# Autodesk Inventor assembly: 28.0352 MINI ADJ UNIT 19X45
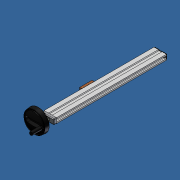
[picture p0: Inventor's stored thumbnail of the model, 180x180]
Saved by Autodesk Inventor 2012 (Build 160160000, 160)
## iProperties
Created: 2015-11
Part Number: 28.0352 MINI ADJ UNIT 19X45
Document SubType Name: Assembly
Designer: Admin
Author: Admin
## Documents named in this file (8)
- C:\Andys Backup Data\ANDY'S INVENTOR\INVENTOR LIBRARIES\PARTS LIBRARY\READY FOR USE MODULES LG\28.0352 MINI ADJ UNIT 19X45.iam
- C:\Andys Backup Data\ANDY'S INVENTOR\INVENTOR LIBRARIES\PARTS LIBRARY\READY FOR USE MODULES LG\SUBCOMPONENTS\28.0352 MINI ADJ UNIT 19X45 PROFILE.ipt
- C:\Andys Backup Data\ANDY'S INVENTOR\INVENTOR LIBRARIES\PARTS LIBRARY\READY FOR USE MODULES LG\28.0350 MINI ADJ UNIT FITTING KIT.iam
- C:\Andys Backup Data\ANDY'S INVENTOR\INVENTOR LIBRARIES\PARTS LIBRARY\END CAPS\22.1001_1 END CAP 19X45.iam
- C:\Andys Backup Data\ANDY'S INVENTOR\INVENTOR LIBRARIES\PARTS LIBRARY\READY FOR USE MODULES LG\SUBCOMPONENTS\28.0212 HANDWHEEL 80mm.iam
- C:\Andys Backup Data\ANDY'S INVENTOR\INVENTOR LIBRARIES\PARTS LIBRARY\READY FOR USE MODULES LG\SUBCOMPONENTS\19.0100_6 BUSHING.ipt
- C:\Andys Backup Data\ANDY'S INVENTOR\INVENTOR LIBRARIES\PARTS LIBRARY\READY FOR USE MODULES LG\SUBCOMPONENTS\28.0366 MINI ADJ BEARING SUPPORT 19X45.ipt
- C:\Andys Backup Data\ANDY'S INVENTOR\INVENTOR LIBRARIES\PARTS LIBRARY\FASTENING ELEMENTS\SCREWS CAP\21.1200 M8X16.ipt
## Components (7 placed, 7 different names)
1. 28.0352 MINI ADJ UNIT 19X45 PROFILE:1 — Insert:1, Angle:1, Insert:2, Angle:4, Angle:5
2. 28.0350 MINI ADJ UNIT FITTING KIT:1 [sub-assembly] — Mate:3, Angle:3, Mate:4, Insert:4, Angle:5
3. 22.1001_1 END CAP 19X45:1 [sub-assembly] — Insert:1, Angle:1
4. 28.0212 HANDWHEEL 80mm:1 [sub-assembly] — Mate:1, Angle:2, Mate:2, Angle:3, Mate:4
5. 19.0100_6 BUSHING:1 — Mate:1, Angle:2, Mate:2, Mate:3
6. 28.0366 MINI ADJ BEARING SUPPORT 19X45:1 — Insert:2, Angle:4, Insert:3, Insert:4
7. 21.1200 M8 x 16:1 — Insert:3
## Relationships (13: Angle 5, Insert 4, Mate 4)
- Insert:1: 28.0352 MINI ADJ UNIT 19X45 PROFILE:1 ↔ 22.1001_1 END CAP 19X45:1
- Angle:1: 28.0352 MINI ADJ UNIT 19X45 PROFILE:1 ↔ 22.1001_1 END CAP 19X45:1
- Mate:1: 28.0212 HANDWHEEL 80mm:1 ↔ 19.0100_6 BUSHING:1
- Angle:2: 28.0212 HANDWHEEL 80mm:1 ↔ 19.0100_6 BUSHING:1
- Mate:2: 28.0212 HANDWHEEL 80mm:1 ↔ 19.0100_6 BUSHING:1
- Mate:3: 28.0350 MINI ADJ UNIT FITTING KIT:1 ↔ 19.0100_6 BUSHING:1
- Angle:3: 28.0350 MINI ADJ UNIT FITTING KIT:1 ↔ 28.0212 HANDWHEEL 80mm:1
- Mate:4: 28.0350 MINI ADJ UNIT FITTING KIT:1 ↔ 28.0212 HANDWHEEL 80mm:1
- Insert:2: 28.0352 MINI ADJ UNIT 19X45 PROFILE:1 ↔ 28.0366 MINI ADJ BEARING SUPPORT 19X45:1
- Angle:4: 28.0352 MINI ADJ UNIT 19X45 PROFILE:1 ↔ 28.0366 MINI ADJ BEARING SUPPORT 19X45:1
- Insert:3: 28.0366 MINI ADJ BEARING SUPPORT 19X45:1 ↔ 21.1200 M8 x 16:1
- Insert:4: 28.0350 MINI ADJ UNIT FITTING KIT:1 ↔ 28.0366 MINI ADJ BEARING SUPPORT 19X45:1
- Angle:5: 28.0352 MINI ADJ UNIT 19X45 PROFILE:1 ↔ 28.0350 MINI ADJ UNIT FITTING KIT:1
